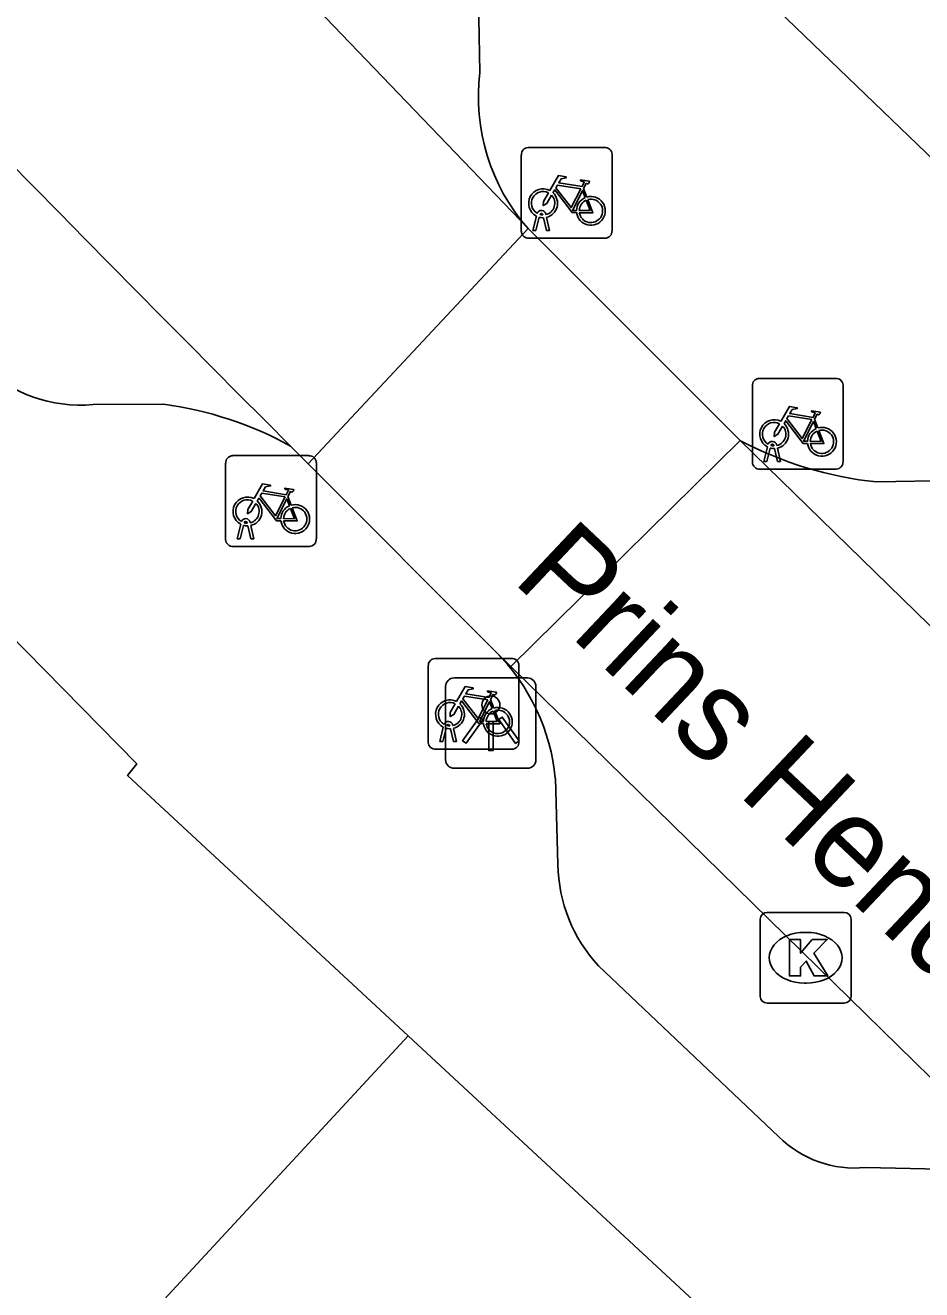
# Model space of a CAD drawing. Extents: x 160664 to 161506, y 382245 to 383288.
# Drawn here: x 160915.24 to 160925.13, y 383117.36 to 383131.29 of the extents above; entities that cross this region are included whole.
import ezdxf

# ---------------------------------------------------------------- set-up
doc = ezdxf.new("R2010")
doc.units = 0
for name, color, linetype in [('IMGEO_Fietsenrek', 7, 'Continuous'), ('IMGEO_Kolk', 7, 'Continuous'), ('IMGEO_Lichtpunt', 7, 'Continuous'), ('IMGEO_Openbare_ruimte_label', 7, 'Continuous'), ('IMGEO_Pand', 7, 'Continuous'), ('IMGEO_Rijbaan_lokaal_open', 7, 'Continuous'), ('IMGEO_Voetpad_open', 7, 'Continuous')]:
    doc.layers.add(name, color=color, linetype=linetype)

msp = doc.modelspace()

# ---------------------------------------------------------------- linework, layer by layer
at = {"layer": 'IMGEO_Fietsenrek'}
for p, q in [((160920.789, 383129.945), (160921.63, 383129.945)), ((160921.63, 383129.945), (160920.789, 383129.945)), ((160921.714, 383129.87), (160921.714, 383129.029)), ((160921.714, 383129.029), (160921.714, 383129.87)), ((160920.714, 383129.02), (160920.714, 383129.861)), ((160920.714, 383129.861), (160920.714, 383129.02)), ((160921.401, 383129.494), (160921.437, 383129.399)), ((160920.841, 383129.029), (160920.88, 383129.189)), ((160920.91, 383129.177), (160920.875, 383129.029)), ((160920.952, 383129.201), (160920.951, 383129.205)), ((160920.993, 383129.029), (160920.959, 383129.171)), ((160920.983, 383129.212), (160920.984, 383129.205)), ((160920.991, 383129.175), (160921.026, 383129.029)), ((160920.875, 383129.029), (160920.841, 383129.029)), ((160921.026, 383129.029), (160920.993, 383129.029)), ((160921.639, 383128.945), (160920.798, 383128.945)), ((160920.798, 383128.945), (160921.639, 383128.945)), ((160923.336, 383127.401), (160924.177, 383127.401)), ((160924.177, 383127.401), (160923.336, 383127.401)), ((160923.261, 383126.476), (160923.261, 383127.317)), ((160923.261, 383127.317), (160923.261, 383126.476)), ((160924.261, 383127.326), (160924.261, 383126.485)), ((160924.261, 383126.485), (160924.261, 383127.326)), ((160923.948, 383126.95), (160923.984, 383126.855)), ((160923.499, 383126.657), (160923.498, 383126.661)), ((160923.53, 383126.668), (160923.531, 383126.661)), ((160917.529, 383126.549), (160918.37, 383126.549)), ((160918.37, 383126.549), (160917.529, 383126.549)), ((160923.388, 383126.485), (160923.427, 383126.645)), ((160923.457, 383126.633), (160923.422, 383126.485)), ((160923.54, 383126.485), (160923.506, 383126.627)), ((160923.538, 383126.631), (160923.573, 383126.485)), ((160917.454, 383125.624), (160917.454, 383126.465)), ((160917.454, 383126.465), (160917.454, 383125.624)), ((160918.454, 383126.474), (160918.454, 383125.633)), ((160918.454, 383125.633), (160918.454, 383126.474)), ((160924.186, 383126.401), (160923.345, 383126.401)), ((160923.345, 383126.401), (160924.186, 383126.401)), ((160923.422, 383126.485), (160923.388, 383126.485)), ((160923.573, 383126.485), (160923.54, 383126.485)), ((160918.141, 383126.098), (160918.177, 383126.003)), ((160917.581, 383125.633), (160917.62, 383125.793)), ((160917.65, 383125.781), (160917.615, 383125.633)), ((160917.692, 383125.805), (160917.691, 383125.809)), ((160917.733, 383125.633), (160917.699, 383125.775)), ((160917.723, 383125.816), (160917.724, 383125.809)), ((160917.731, 383125.779), (160917.766, 383125.633)), ((160918.379, 383125.549), (160917.538, 383125.549)), ((160917.538, 383125.549), (160918.379, 383125.549)), ((160917.615, 383125.633), (160917.581, 383125.633)), ((160917.766, 383125.633), (160917.733, 383125.633)), ((160919.763, 383124.314), (160920.604, 383124.314)), ((160920.604, 383124.314), (160919.763, 383124.314)), ((160919.688, 383123.389), (160919.688, 383124.23)), ((160919.688, 383124.23), (160919.688, 383123.389)), ((160920.688, 383124.239), (160920.688, 383123.398)), ((160920.688, 383123.398), (160920.688, 383124.239)), ((160920.375, 383123.863), (160920.411, 383123.768)), ((160919.815, 383123.398), (160919.854, 383123.558)), ((160919.884, 383123.546), (160919.849, 383123.398)), ((160919.926, 383123.57), (160919.925, 383123.574)), ((160919.967, 383123.398), (160919.933, 383123.54)), ((160919.957, 383123.581), (160919.958, 383123.574)), ((160919.965, 383123.544), (160920, 383123.398)), ((160920.613, 383123.314), (160919.772, 383123.314)), ((160919.772, 383123.314), (160920.613, 383123.314)), ((160919.849, 383123.398), (160919.815, 383123.398)), ((160920, 383123.398), (160919.967, 383123.398))]:
    msp.add_line(p, q, dxfattribs=at)
for points in [[(160921.027, 383129.471), (160921.122, 383129.635), (160921.208, 383129.621), (160921.21, 383129.612), (160921.154, 383129.601), (160921.127, 383129.556), (160921.383, 383129.515)], [(160921.383, 383129.515), (160921.408, 383129.564), (160921.402, 383129.568), (160921.379, 383129.572), (160921.367, 383129.579), (160921.366, 383129.582), (160921.368, 383129.587), (160921.463, 383129.572), (160921.465, 383129.562), (160921.455, 383129.549), (160921.443, 383129.543), (160921.429, 383129.549), (160921.401, 383129.494)], [(160921.048, 383129.419), (160920.996, 383129.329), (160920.956, 383129.304), (160920.957, 383129.351), (160921.012, 383129.445)], [(160921.323, 383129.227), (160921.273, 383129.227), (160921.082, 383129.478), (160921.063, 383129.446)], [(160921.37, 383129.49), (160921.113, 383129.531), (160921.096, 383129.502), (160921.263, 383129.282), (160921.37, 383129.49)], [(160921.418, 383129.392), (160921.388, 383129.469), (160921.279, 383129.251), (160921.322, 383129.251)], [(160921.352, 383129.251), (160921.472, 383129.25), (160921.428, 383129.364)], [(160921.448, 383129.371), (160921.503, 383129.226), (160921.353, 383129.226)], [(160923.574, 383126.927), (160923.669, 383127.091), (160923.755, 383127.077), (160923.757, 383127.068), (160923.701, 383127.057), (160923.674, 383127.012), (160923.93, 383126.971)], [(160923.917, 383126.946), (160923.66, 383126.987), (160923.643, 383126.958), (160923.81, 383126.738), (160923.917, 383126.946)], [(160923.93, 383126.971), (160923.955, 383127.02), (160923.949, 383127.024), (160923.926, 383127.028), (160923.914, 383127.035), (160923.913, 383127.038), (160923.915, 383127.043), (160924.01, 383127.028), (160924.012, 383127.018), (160924.002, 383127.005), (160923.99, 383126.999), (160923.976, 383127.005), (160923.948, 383126.95)], [(160923.595, 383126.875), (160923.543, 383126.785), (160923.503, 383126.76), (160923.504, 383126.807), (160923.559, 383126.901)], [(160923.87, 383126.683), (160923.82, 383126.683), (160923.629, 383126.934), (160923.61, 383126.902)], [(160923.965, 383126.848), (160923.935, 383126.925), (160923.826, 383126.707), (160923.869, 383126.707)], [(160923.899, 383126.707), (160924.019, 383126.706), (160923.975, 383126.82)], [(160923.995, 383126.827), (160924.05, 383126.682), (160923.9, 383126.682)], [(160917.767, 383126.075), (160917.862, 383126.239), (160917.948, 383126.225), (160917.95, 383126.216), (160917.894, 383126.205), (160917.867, 383126.16), (160918.123, 383126.119)], [(160918.11, 383126.094), (160917.853, 383126.135), (160917.836, 383126.106), (160918.003, 383125.886), (160918.11, 383126.094)], [(160918.123, 383126.119), (160918.148, 383126.168), (160918.142, 383126.172), (160918.119, 383126.176), (160918.107, 383126.183), (160918.106, 383126.186), (160918.108, 383126.191), (160918.203, 383126.176), (160918.205, 383126.166), (160918.195, 383126.153), (160918.183, 383126.147), (160918.169, 383126.153), (160918.141, 383126.098)], [(160917.788, 383126.023), (160917.736, 383125.933), (160917.696, 383125.908), (160917.697, 383125.955), (160917.752, 383126.049)], [(160918.063, 383125.831), (160918.013, 383125.831), (160917.822, 383126.082), (160917.803, 383126.05)], [(160918.158, 383125.996), (160918.128, 383126.073), (160918.019, 383125.855), (160918.062, 383125.855)], [(160918.092, 383125.855), (160918.212, 383125.854), (160918.168, 383125.968)], [(160918.188, 383125.975), (160918.243, 383125.83), (160918.093, 383125.83)], [(160920.001, 383123.84), (160920.096, 383124.004), (160920.182, 383123.99), (160920.184, 383123.981), (160920.128, 383123.97), (160920.101, 383123.925), (160920.357, 383123.884)], [(160920.344, 383123.859), (160920.087, 383123.9), (160920.07, 383123.871), (160920.237, 383123.651), (160920.344, 383123.859)], [(160920.357, 383123.884), (160920.382, 383123.933), (160920.376, 383123.937), (160920.353, 383123.941), (160920.341, 383123.948), (160920.34, 383123.951), (160920.342, 383123.956), (160920.437, 383123.941), (160920.439, 383123.931), (160920.429, 383123.918), (160920.417, 383123.912), (160920.403, 383123.918), (160920.375, 383123.863)], [(160920.022, 383123.788), (160919.97, 383123.698), (160919.93, 383123.673), (160919.931, 383123.72), (160919.986, 383123.814)], [(160920.297, 383123.596), (160920.247, 383123.596), (160920.056, 383123.847), (160920.037, 383123.815)], [(160920.392, 383123.761), (160920.362, 383123.838), (160920.253, 383123.62), (160920.296, 383123.62)], [(160920.326, 383123.62), (160920.446, 383123.619), (160920.402, 383123.733)], [(160920.422, 383123.74), (160920.477, 383123.595), (160920.327, 383123.595)]]:
    msp.add_lwpolyline(points, dxfattribs=at)
for centre, radius, start, end in [((160920.792, 383129.867), 0.0779, 92.4484, 184.2845), ((160920.792, 383129.867), 0.0779, 92.4484, 184.2845), ((160921.636, 383129.867), 0.0779, 2.4484, 94.2845), ((160921.636, 383129.867), 0.0779, 2.4484, 94.2845), ((160920.954, 383129.33), 0.159, 62.6766, 242.1369), ((160920.954, 383129.33), 0.129, 63.3192, 238.903), ((160920.954, 383129.33), 0.159, 283.5766, 46.6042), ((160920.954, 383129.33), 0.129, 283.6043, 43.4302), ((160921.481, 383129.246), 0.159, 113.3408, 178.3217), ((160921.481, 383129.246), 0.159, 187.0065, 105.7708), ((160921.481, 383129.246), 0.129, 113.923, 177.9556), ((160921.481, 383129.246), 0.129, 188.6715, 104.5883), ((160920.934, 383129.201), 0.0499, 12.8025, 158.6934), ((160920.954, 383129.33), 0.159, 253.9967, 271.7867), ((160920.934, 383129.201), 0.0174, 12.8025, 163.4502), ((160920.954, 383129.33), 0.129, 253.415, 269.0204), ((160921.636, 383129.023), 0.0779, 272.4484, 4.2845), ((160921.636, 383129.023), 0.0779, 272.4484, 4.2845), ((160920.792, 383129.023), 0.0779, 182.4484, 274.2845), ((160920.792, 383129.023), 0.0779, 182.4484, 274.2845), ((160923.339, 383127.323), 0.0779, 92.4484, 184.2845), ((160923.339, 383127.323), 0.0779, 92.4484, 184.2845), ((160924.183, 383127.323), 0.0779, 2.4484, 94.2845), ((160924.183, 383127.323), 0.0779, 2.4484, 94.2845), ((160923.501, 383126.786), 0.159, 62.6766, 242.1369), ((160923.501, 383126.786), 0.129, 63.3192, 238.903), ((160923.501, 383126.786), 0.129, 283.6043, 43.4302), ((160923.501, 383126.786), 0.159, 283.5766, 46.6042), ((160924.028, 383126.702), 0.159, 113.3408, 178.3217), ((160924.028, 383126.702), 0.159, 187.0065, 105.7708), ((160924.028, 383126.702), 0.129, 113.923, 177.9556), ((160924.028, 383126.702), 0.129, 188.6715, 104.5883), ((160923.481, 383126.657), 0.0499, 12.8025, 158.6934), ((160923.481, 383126.657), 0.0174, 12.8025, 163.4502), ((160923.501, 383126.786), 0.129, 253.415, 269.0204), ((160917.532, 383126.471), 0.0779, 92.4484, 184.2845), ((160917.532, 383126.471), 0.0779, 92.4484, 184.2845), ((160918.376, 383126.471), 0.0779, 2.4484, 94.2845), ((160918.376, 383126.471), 0.0779, 2.4484, 94.2845), ((160923.501, 383126.786), 0.159, 253.9967, 271.7867), ((160923.339, 383126.479), 0.0779, 182.4484, 274.2845), ((160923.339, 383126.479), 0.0779, 182.4484, 274.2845), ((160924.183, 383126.479), 0.0779, 272.4484, 4.2845), ((160924.183, 383126.479), 0.0779, 272.4484, 4.2845), ((160917.694, 383125.934), 0.159, 62.6766, 242.1369), ((160917.694, 383125.934), 0.129, 63.3192, 238.903), ((160917.694, 383125.934), 0.129, 283.6043, 43.4302), ((160917.694, 383125.934), 0.159, 283.5766, 46.6042), ((160918.221, 383125.85), 0.159, 113.3408, 178.3217), ((160918.221, 383125.85), 0.159, 187.0065, 105.7708), ((160918.221, 383125.85), 0.129, 113.923, 177.9556), ((160918.221, 383125.85), 0.129, 188.6715, 104.5883), ((160917.674, 383125.805), 0.0499, 12.8025, 158.6934), ((160917.674, 383125.805), 0.0174, 12.8025, 163.4502), ((160917.694, 383125.934), 0.159, 253.9967, 271.7867), ((160917.694, 383125.934), 0.129, 253.415, 269.0204), ((160917.532, 383125.627), 0.0779, 182.4484, 274.2845), ((160917.532, 383125.627), 0.0779, 182.4484, 274.2845), ((160918.376, 383125.627), 0.0779, 272.4484, 4.2845), ((160918.376, 383125.627), 0.0779, 272.4484, 4.2845), ((160919.766, 383124.236), 0.0779, 92.4484, 184.2845), ((160919.766, 383124.236), 0.0779, 92.4484, 184.2845), ((160920.61, 383124.236), 0.0779, 2.4484, 94.2845), ((160920.61, 383124.236), 0.0779, 2.4484, 94.2845), ((160919.928, 383123.699), 0.159, 62.6766, 242.1369), ((160919.928, 383123.699), 0.129, 63.3192, 238.903), ((160919.928, 383123.699), 0.129, 283.6043, 43.4302), ((160919.928, 383123.699), 0.159, 283.5766, 46.6042), ((160920.455, 383123.615), 0.159, 113.3408, 178.3217), ((160920.455, 383123.615), 0.159, 187.0065, 105.7708), ((160920.455, 383123.615), 0.129, 113.923, 177.9556), ((160920.455, 383123.615), 0.129, 188.6715, 104.5883), ((160919.908, 383123.57), 0.0499, 12.8025, 158.6934), ((160919.928, 383123.699), 0.159, 253.9967, 271.7867), ((160919.908, 383123.57), 0.0174, 12.8025, 163.4502), ((160919.928, 383123.699), 0.129, 253.415, 269.0204), ((160919.766, 383123.392), 0.0779, 182.4484, 274.2845), ((160919.766, 383123.392), 0.0779, 182.4484, 274.2845), ((160920.61, 383123.392), 0.0779, 272.4484, 4.2845), ((160920.61, 383123.392), 0.0779, 272.4484, 4.2845)]:
    msp.add_arc(centre, radius, start, end, dxfattribs=at)
at = {"layer": 'IMGEO_Kolk'}
for p, q in [((160923.423, 383121.516), (160924.275, 383121.516)), ((160923.348, 383120.59), (160923.348, 383121.442)), ((160924.349, 383121.442), (160924.349, 383120.59)), ((160923.836, 383121.296), (160923.861, 383121.296)), ((160923.859, 383120.736), (160923.834, 383120.736)), ((160924.275, 383120.516), (160923.423, 383120.516))]:
    msp.add_line(p, q, dxfattribs=at)
for points in [[(160923.423, 383121.516), (160924.275, 383121.516)], [(160923.348, 383120.59), (160923.348, 383121.442)], [(160924.349, 383121.442), (160924.349, 383120.59)], [(160923.669, 383121.216), (160923.792, 383121.216), (160923.792, 383121.065), (160923.922, 383121.216), (160924.086, 383121.216), (160923.94, 383121.065), (160924.093, 383120.816), (160923.941, 383120.816), (160923.856, 383120.98), (160923.792, 383120.913), (160923.792, 383120.816), (160923.669, 383120.816), (160923.669, 383121.216)], [(160924.275, 383120.516), (160923.423, 383120.516)]]:
    msp.add_lwpolyline(points, dxfattribs=at)
for centre, start, end in [((160923.425, 383121.44), 91.552, 178.448), ((160923.425, 383121.44), 91.552, 178.448), ((160924.273, 383121.44), 1.552, 88.448), ((160924.273, 383121.44), 1.552, 88.448), ((160923.425, 383120.592), 181.552, 268.448), ((160923.425, 383120.592), 181.552, 268.448), ((160924.273, 383120.592), 271.552, 358.448), ((160924.273, 383120.592), 271.552, 358.448)]:
    msp.add_arc(centre, 0.0765, start, end, dxfattribs=at)
for centre, major_axis, ratio, start_param, end_param in [((160923.835, 383121.016), (-0.387, 0.002), 0.722429, 4.712389, 7.853982), ((160923.86, 383121.016), (-0.39, 0.002), 0.717154, 1.570796, 4.712389)]:
    msp.add_ellipse(centre, major_axis=major_axis, ratio=ratio, start_param=start_param, end_param=end_param, dxfattribs=at)
at = {"layer": 'IMGEO_Lichtpunt'}
for p, q in [((160920.781, 383124.1), (160919.973, 383124.1)), ((160920.781, 383124.1), (160919.973, 383124.1)), ((160919.879, 383124.005), (160919.879, 383123.198)), ((160919.879, 383124.005), (160919.879, 383123.198)), ((160920.875, 383123.198), (160920.875, 383124.005)), ((160920.875, 383123.198), (160920.875, 383124.005)), ((160919.973, 383123.104), (160920.781, 383123.104)), ((160919.973, 383123.104), (160920.781, 383123.104))]:
    msp.add_line(p, q, dxfattribs=at)
for points in [[(160920.253, 383123.669), (160920.292, 383123.641), (160920.104, 383123.379), (160920.066, 383123.406), (160920.253, 383123.669)], [(160920.355, 383123.621), (160920.402, 383123.621), (160920.402, 383123.299), (160920.355, 383123.299), (160920.355, 383123.621)], [(160920.465, 383123.641), (160920.503, 383123.668), (160920.69, 383123.406), (160920.651, 383123.378), (160920.465, 383123.641)]]:
    msp.add_lwpolyline(points, dxfattribs=at)
msp.add_circle((160920.378, 383123.803), 0.0994, dxfattribs=at)
for centre, start, end in [((160919.973, 383124.005), 90, 180), ((160919.973, 383124.005), 90, 180), ((160920.781, 383124.005), 0, 90), ((160920.781, 383124.005), 0, 90), ((160919.973, 383123.198), 180, 270), ((160919.973, 383123.198), 180, 270), ((160920.781, 383123.198), 270, 0), ((160920.781, 383123.198), 270, 360)]:
    msp.add_arc(centre, 0.0946, start, end, dxfattribs=at)
at = {"layer": 'IMGEO_Pand'}
for points in [[(160925.467, 383129.608), (160920.856, 383134.043), (160920.779, 383134.126)], [(160910.58, 383129.146), (160916.474, 383123.152), (160916.373, 383123.023), (160919.466, 383120.156)], [(160911.568, 383111.629), (160919.466, 383120.156)], [(160919.466, 383120.156), (160922.714, 383117.145), (160922.774, 383117.225), (160924.955, 383115.295)]]:
    msp.add_lwpolyline(points, dxfattribs=at)
at = {"layer": 'IMGEO_Rijbaan_lokaal_open'}
for points in [[(160920.788, 383129.051), (160908.282, 383142.065)], [(160918.364, 383126.459), (160920.788, 383129.051)], [(160920.788, 383129.051), (160923.125, 383126.717)], [(160923.125, 383126.717), (160920.598, 383124.224)], [(160929.824, 383120.189), (160923.125, 383126.717)], [(160918.364, 383126.459), (160918.17, 383126.654)], [(160920.433, 383124.388), (160918.364, 383126.459)], [(160920.598, 383124.224), (160920.433, 383124.388)], [(160920.598, 383124.224), (160926.648, 383118.305)]]:
    msp.add_lwpolyline(points, dxfattribs=at)
msp.add_arc((161242.258, 383450.551), 458.195, 221.76429, 224.98305, dxfattribs=at)
at = {"layer": 'IMGEO_Voetpad_open'}
for points in [[(160920.242, 383131.572), (160920.258, 383130.773)], [(160916.769, 383127.115), (160915.995, 383127.112)], [(160924.63, 383126.259), (160925.48, 383126.275)], [(160921.118, 383122.042), (160921.089, 383122.994)], [(160923.554, 383119.044), (160921.566, 383120.927)], [(160925.497, 383118.683), (160924.507, 383118.705)]]:
    msp.add_lwpolyline(points, dxfattribs=at)
for centre, radius, start, end in [((160922.434, 383130.5), 2.193, 172.8521, 221.3627), ((160915.857, 383128.708), 1.602, 226.2473, 274.9352), ((160916.247, 383123.171), 3.979, 61.1049, 82.4674), ((160925.065, 383130.391), 4.155, 242.1603, 263.9877), ((160918.814, 383122.775), 2.285, 5.5006, 44.9017), ((160922.786, 383122.065), 1.668, 180.7758, 223.0041), ((160924.387, 383119.876), 1.177, 224.9732, 275.8639)]:
    msp.add_arc(centre, radius, start, end, dxfattribs=at)

# ---------------------------------------------------------------- texts
at = {"layer": 'IMGEO_Openbare_ruimte_label'}
msp.add_text('Prins Hendrikstraat', height=1, rotation=316.662, dxfattribs=at).set_placement((160920.601, 383125.171))

doc.saveas('drawing.dxf')
